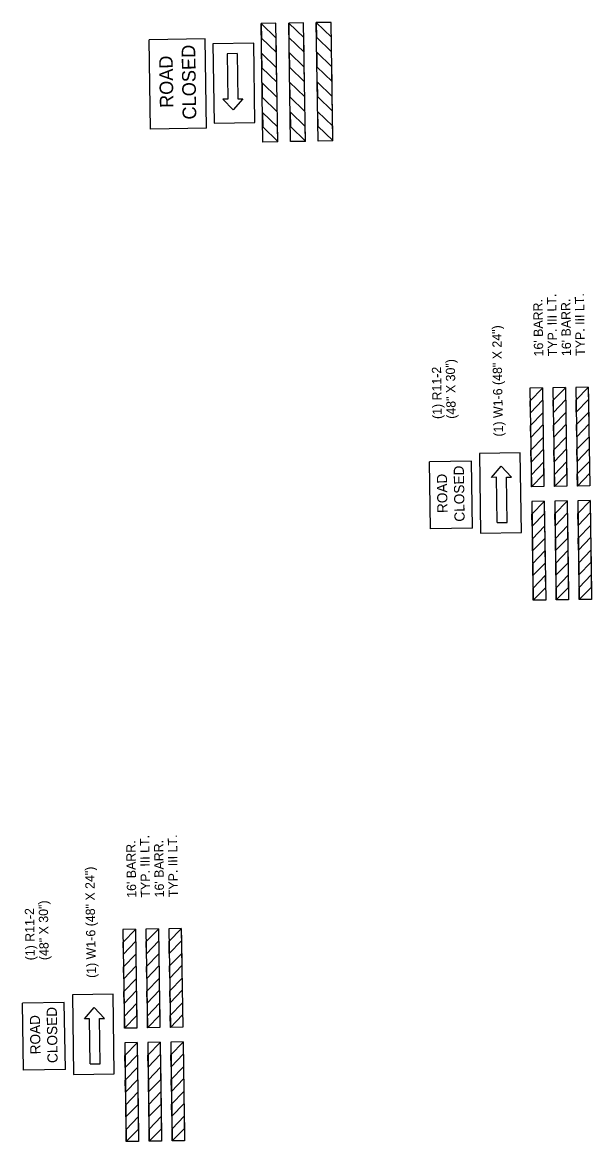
# Model space of a CAD drawing. Extents: x 1770139 to 1773492, y 718230 to 727190.
# Drawn here: x 1773099 to 1773468, y 718477 to 719202 of the extents above; entities that cross this region are included whole.
import ezdxf

# ---------------------------------------------------------------- set-up
doc = ezdxf.new("R2010")
doc.units = 0
doc.layers.add('R_MOT', color=7, linetype='Continuous')

msp = doc.modelspace()

# ---------------------------------------------------------------- linework, layer by layer
at = {"layer": 'R_MOT'}
for p, q in [((1773263.38, 719201.45), (1773253.73, 719201.3)), ((1773254.92, 719124.43), (1773253.73, 719201.3)), ((1773263.36, 719201.39), (1773263.3, 719201.45)), ((1773264.57, 719124.58), (1773263.38, 719201.45)), ((1773281.25, 719201.72), (1773271.62, 719201.58)), ((1773281.25, 719201.72), (1773271.62, 719201.58)), ((1773272.81, 719124.71), (1773271.62, 719201.58)), ((1773282.43, 719124.86), (1773281.25, 719201.72)), ((1773299.08, 719202), (1773289.46, 719201.85)), ((1773290.64, 719124.98), (1773289.46, 719201.85)), ((1773300.26, 719125.13), (1773299.08, 719202)), ((1773217.53, 719191.29), (1773181.32, 719190.73)), ((1773182.22, 719132.77), (1773181.32, 719190.73)), ((1773218.42, 719133.33), (1773217.53, 719191.29)), ((1773238.26, 719181.82), (1773231.72, 719181.72)), ((1773231.72, 719181.72), (1773232.17, 719152.33)), ((1773238.26, 719181.82), (1773238.72, 719152.43)), ((1773232.17, 719152.33), (1773228.9, 719152.28)), ((1773235.55, 719145.21), (1773228.9, 719152.28)), ((1773241.99, 719152.48), (1773235.55, 719145.21)), ((1773238.72, 719152.43), (1773241.99, 719152.48)), ((1773218.42, 719133.33), (1773182.22, 719132.77)), ((1773300.26, 719125.13), (1773290.64, 719124.98)), ((1773264.57, 719124.58), (1773254.92, 719124.43)), ((1773282.43, 719124.86), (1773272.81, 719124.71)), ((1773465.62, 718965.53), (1773457.61, 718965.41)), ((1773457.61, 718965.41), (1773458.59, 718901.39)), ((1773465.62, 718965.53), (1773466.61, 718901.51)), ((1773435.89, 718965.08), (1773427.85, 718964.95)), ((1773427.85, 718964.95), (1773428.84, 718900.93)), ((1773435.89, 718965.08), (1773436.87, 718901.05)), ((1773450.77, 718965.3), (1773442.75, 718965.18)), ((1773442.75, 718965.18), (1773443.74, 718901.16)), ((1773450.77, 718965.3), (1773451.75, 718901.28)), ((1773389.88, 718917.52), (1773362.74, 718917.11)), ((1773363.41, 718873.66), (1773362.74, 718917.11)), ((1773390.55, 718874.08), (1773389.88, 718917.52)), ((1773402.84, 718907.06), (1773409.27, 718914.33)), ((1773409.27, 718914.33), (1773415.93, 718907.26)), ((1773406.11, 718907.11), (1773402.84, 718907.06)), ((1773406.56, 718877.72), (1773406.11, 718907.11)), ((1773412.65, 718907.21), (1773415.93, 718907.26)), ((1773413.11, 718877.82), (1773412.65, 718907.21)), ((1773436.87, 718901.05), (1773428.84, 718900.93)), ((1773436.85, 718901.1), (1773436.8, 718901.05)), ((1773451.75, 718901.28), (1773443.74, 718901.16)), ((1773451.75, 718901.28), (1773443.74, 718901.16)), ((1773466.61, 718901.51), (1773458.59, 718901.39)), ((1773437.02, 718891.55), (1773428.98, 718891.43)), ((1773428.98, 718891.43), (1773429.97, 718827.41)), ((1773437.02, 718891.55), (1773438.01, 718827.53)), ((1773451.9, 718891.78), (1773443.88, 718891.66)), ((1773443.88, 718891.66), (1773444.87, 718827.63)), ((1773451.9, 718891.78), (1773452.89, 718827.76)), ((1773466.75, 718892.01), (1773458.74, 718891.89)), ((1773458.74, 718891.89), (1773459.72, 718827.86)), ((1773466.75, 718892.01), (1773467.74, 718827.99)), ((1773390.55, 718874.08), (1773363.41, 718873.66)), ((1773406.56, 718877.72), (1773413.11, 718877.82)), ((1773437.98, 718827.58), (1773437.94, 718827.53)), ((1773452.89, 718827.76), (1773444.87, 718827.63)), ((1773452.89, 718827.76), (1773444.87, 718827.63)), ((1773467.74, 718827.99), (1773459.72, 718827.86)), ((1773438.01, 718827.53), (1773429.97, 718827.41)), ((1773172.33, 718614.17), (1773164.29, 718614.05)), ((1773164.29, 718614.05), (1773165.27, 718550.03)), ((1773172.33, 718614.17), (1773173.31, 718550.15)), ((1773187.21, 718614.4), (1773179.19, 718614.28)), ((1773179.19, 718614.28), (1773180.18, 718550.26)), ((1773187.21, 718614.4), (1773188.19, 718550.38)), ((1773202.06, 718614.63), (1773194.04, 718614.51)), ((1773194.04, 718614.51), (1773195.03, 718550.48)), ((1773202.06, 718614.63), (1773203.05, 718550.61)), ((1773126.32, 718566.62), (1773099.18, 718566.21)), ((1773126.99, 718523.18), (1773126.32, 718566.62)), ((1773099.85, 718522.76), (1773099.18, 718566.21)), ((1773139.28, 718556.15), (1773145.71, 718563.43)), ((1773145.71, 718563.43), (1773152.37, 718556.36)), ((1773142.55, 718556.2), (1773139.28, 718556.15)), ((1773143, 718526.82), (1773142.55, 718556.2)), ((1773149.09, 718556.31), (1773152.37, 718556.36)), ((1773149.55, 718526.92), (1773149.09, 718556.31)), ((1773173.31, 718550.15), (1773165.27, 718550.03)), ((1773173.29, 718550.2), (1773173.24, 718550.15)), ((1773188.19, 718550.38), (1773180.18, 718550.26)), ((1773188.19, 718550.38), (1773180.18, 718550.26)), ((1773203.05, 718550.61), (1773195.03, 718550.48)), ((1773173.46, 718540.65), (1773165.42, 718540.53)), ((1773165.42, 718540.53), (1773166.41, 718476.5)), ((1773173.46, 718540.65), (1773174.45, 718476.63)), ((1773188.34, 718540.88), (1773180.32, 718540.76)), ((1773180.32, 718540.76), (1773181.31, 718476.73)), ((1773188.34, 718540.88), (1773189.32, 718476.86)), ((1773203.19, 718541.11), (1773195.18, 718540.99)), ((1773195.18, 718540.99), (1773196.16, 718476.96)), ((1773203.19, 718541.11), (1773204.18, 718477.09)), ((1773126.99, 718523.18), (1773099.85, 718522.76)), ((1773143, 718526.82), (1773149.55, 718526.92)), ((1773174.45, 718476.63), (1773166.41, 718476.5)), ((1773174.42, 718476.68), (1773174.37, 718476.63)), ((1773189.32, 718476.86), (1773181.31, 718476.73)), ((1773189.32, 718476.86), (1773181.31, 718476.73)), ((1773204.18, 718477.09), (1773196.16, 718476.96))]:
    msp.add_line(p, q, dxfattribs=at)
for points in [[(1773253.73, 719201.3), (1773253.91, 719191.85), (1773263.65, 719182.4), (1773263.5, 719191.83)], [(1773271.62, 719201.58), (1773271.8, 719192.13), (1773281.54, 719182.68), (1773281.39, 719192.1)], [(1773289.46, 719201.85), (1773289.63, 719192.4), (1773299.37, 719182.95), (1773299.23, 719192.38)], [(1773249.72, 719137.03), (1773248.93, 719188.55), (1773222.58, 719188.15), (1773223.37, 719136.62)], [(1773254.03, 719182.09), (1773254.2, 719172.64), (1773263.94, 719163.2), (1773263.8, 719172.62)], [(1773271.92, 719182.37), (1773272.09, 719172.92), (1773281.84, 719163.47), (1773281.69, 719172.89)], [(1773289.75, 719182.64), (1773289.93, 719173.19), (1773299.67, 719163.75), (1773299.52, 719173.17)], [(1773254.32, 719162.89), (1773254.5, 719153.44), (1773264.24, 719143.99), (1773264.09, 719153.41)], [(1773272.22, 719163.16), (1773272.39, 719153.71), (1773282.13, 719144.27), (1773281.99, 719153.69)], [(1773290.05, 719163.44), (1773290.22, 719153.99), (1773299.97, 719144.54), (1773299.82, 719153.96)], [(1773254.62, 719143.68), (1773254.79, 719134.23), (1773264.54, 719124.78), (1773264.39, 719134.2)], [(1773272.51, 719143.95), (1773272.69, 719134.5), (1773282.43, 719125.06), (1773282.28, 719134.48)], [(1773290.35, 719144.23), (1773290.52, 719134.78), (1773300.26, 719125.33), (1773300.12, 719134.75)], [(1773428.1, 718948.92), (1773428, 718956.79), (1773435.87, 718964.91), (1773435.99, 718957.06)], [(1773443, 718949.15), (1773442.9, 718957.02), (1773450.77, 718965.14), (1773450.89, 718957.29)], [(1773457.85, 718949.38), (1773457.76, 718957.25), (1773465.62, 718965.37), (1773465.74, 718957.52)], [(1773428.34, 718932.92), (1773428.24, 718940.79), (1773436.11, 718948.91), (1773436.23, 718941.06)], [(1773443.24, 718933.15), (1773443.15, 718941.02), (1773451.02, 718949.14), (1773451.14, 718941.29)], [(1773458.1, 718933.38), (1773458, 718941.25), (1773465.87, 718949.37), (1773465.99, 718941.52)], [(1773428.59, 718916.93), (1773428.49, 718924.8), (1773436.36, 718932.91), (1773436.48, 718925.06)], [(1773443.49, 718917.15), (1773443.39, 718925.03), (1773451.26, 718933.14), (1773451.38, 718925.29)], [(1773458.35, 718917.38), (1773458.25, 718925.26), (1773466.12, 718933.37), (1773466.24, 718925.52)], [(1773395.11, 718922.51), (1773395.9, 718870.99), (1773422.25, 718871.39), (1773421.46, 718922.92)], [(1773428.84, 718900.93), (1773428.74, 718908.8), (1773436.61, 718916.91), (1773436.73, 718909.07)], [(1773443.74, 718901.16), (1773443.64, 718909.03), (1773451.51, 718917.14), (1773451.63, 718909.3)], [(1773458.59, 718901.39), (1773458.49, 718909.26), (1773466.36, 718917.37), (1773466.48, 718909.52)], [(1773429.23, 718875.4), (1773429.13, 718883.27), (1773437, 718891.39), (1773437.12, 718883.54)], [(1773444.13, 718875.63), (1773444.03, 718883.5), (1773451.9, 718891.62), (1773452.02, 718883.77)], [(1773458.99, 718875.86), (1773458.89, 718883.73), (1773466.76, 718891.84), (1773466.88, 718884)], [(1773429.48, 718859.4), (1773429.38, 718867.27), (1773437.25, 718875.39), (1773437.37, 718867.54)], [(1773444.38, 718859.63), (1773444.28, 718867.5), (1773452.15, 718875.62), (1773452.27, 718867.77)], [(1773459.23, 718859.86), (1773459.13, 718867.73), (1773467, 718875.85), (1773467.12, 718868)], [(1773429.72, 718843.4), (1773429.62, 718851.27), (1773437.49, 718859.39), (1773437.61, 718851.54)], [(1773444.62, 718843.63), (1773444.53, 718851.5), (1773452.39, 718859.62), (1773452.52, 718851.77)], [(1773459.48, 718843.86), (1773459.38, 718851.73), (1773467.25, 718859.85), (1773467.37, 718852)], [(1773429.97, 718827.41), (1773429.87, 718835.28), (1773437.74, 718843.39), (1773437.86, 718835.54)], [(1773444.87, 718827.63), (1773444.77, 718835.51), (1773452.64, 718843.62), (1773452.76, 718835.77)], [(1773459.72, 718827.86), (1773459.63, 718835.74), (1773467.5, 718843.85), (1773467.62, 718836)], [(1773164.53, 718598.02), (1773164.44, 718605.89), (1773172.31, 718614.01), (1773172.43, 718606.16)], [(1773179.44, 718598.25), (1773179.34, 718606.12), (1773187.21, 718614.24), (1773187.33, 718606.39)], [(1773194.29, 718598.48), (1773194.19, 718606.35), (1773202.06, 718614.46), (1773202.18, 718606.62)], [(1773164.78, 718582.02), (1773164.68, 718589.89), (1773172.55, 718598.01), (1773172.67, 718590.16)], [(1773179.68, 718582.25), (1773179.59, 718590.12), (1773187.45, 718598.24), (1773187.58, 718590.39)], [(1773194.54, 718582.48), (1773194.44, 718590.35), (1773202.31, 718598.47), (1773202.43, 718590.62)], [(1773165.03, 718566.02), (1773164.93, 718573.9), (1773172.8, 718582.01), (1773172.92, 718574.16)], [(1773179.93, 718566.25), (1773179.83, 718574.13), (1773187.7, 718582.24), (1773187.82, 718574.39)], [(1773194.78, 718566.48), (1773194.69, 718574.35), (1773202.56, 718582.47), (1773202.68, 718574.62)], [(1773131.54, 718571.61), (1773132.34, 718520.09), (1773158.69, 718520.49), (1773157.89, 718572.02)], [(1773195.03, 718550.48), (1773194.93, 718558.36), (1773202.8, 718566.47), (1773202.92, 718558.62)], [(1773165.27, 718550.03), (1773165.18, 718557.9), (1773173.04, 718566.01), (1773173.17, 718558.16)], [(1773180.18, 718550.26), (1773180.08, 718558.13), (1773187.95, 718566.24), (1773188.07, 718558.39)], [(1773165.67, 718524.5), (1773165.57, 718532.37), (1773173.44, 718540.48), (1773173.56, 718532.64)], [(1773180.57, 718524.73), (1773180.47, 718532.6), (1773188.34, 718540.71), (1773188.46, 718532.87)], [(1773195.42, 718524.96), (1773195.33, 718532.83), (1773203.19, 718540.94), (1773203.32, 718533.1)], [(1773165.91, 718508.5), (1773165.82, 718516.37), (1773173.68, 718524.49), (1773173.81, 718516.64)], [(1773180.82, 718508.73), (1773180.72, 718516.6), (1773188.59, 718524.72), (1773188.71, 718516.87)], [(1773195.67, 718508.96), (1773195.57, 718516.83), (1773203.44, 718524.94), (1773203.56, 718517.1)], [(1773166.16, 718492.5), (1773166.06, 718500.37), (1773173.93, 718508.49), (1773174.05, 718500.64)], [(1773181.06, 718492.73), (1773180.97, 718500.6), (1773188.83, 718508.72), (1773188.95, 718500.87)], [(1773195.92, 718492.96), (1773195.82, 718500.83), (1773203.69, 718508.95), (1773203.81, 718501.1)], [(1773166.41, 718476.5), (1773166.31, 718484.38), (1773174.18, 718492.49), (1773174.3, 718484.64)], [(1773181.31, 718476.73), (1773181.21, 718484.61), (1773189.08, 718492.72), (1773189.2, 718484.87)], [(1773196.16, 718476.96), (1773196.07, 718484.83), (1773203.93, 718492.95), (1773204.06, 718485.1)]]:
    msp.add_lwpolyline(points, close=True, dxfattribs=at)

# ---------------------------------------------------------------- texts
for s, height, p in [('CLOSED', 8.817, (1773211.79, 719139.08)), ('ROAD', 8.774, (1773196.98, 719146.63)), ('TYP. III LT.', 6, (1773445.46, 718985.63)), ('TYP. III LT.', 6, (1773463.46, 718985.91)), ("16' BARR.", 6, (1773436.46, 718985.49)), ("16' BARR.", 6, (1773454.46, 718985.77)), ('(1) W1-6 (48" X 24")', 6, (1773410.39, 718933.57)), ('(48" X 30")', 6, (1773379.81, 718945.09)), ('(1) R11-2', 6, (1773370.81, 718944.95)), ('ROAD', 6.577, (1773374.48, 718884.05)), ('CLOSED', 6.61, (1773385.58, 718878.39)), ("16' BARR.", 6, (1773172.9, 718634.59)), ('TYP. III LT.', 6, (1773181.9, 718634.73)), ("16' BARR.", 6, (1773190.9, 718634.87)), ('TYP. III LT.', 6, (1773199.9, 718635.01)), ('(1) W1-6 (48" X 24")', 6, (1773146.83, 718582.67)), ('(48" X 30")', 6, (1773116.25, 718594.19)), ('(1) R11-2', 6, (1773107.25, 718594.05)), ('CLOSED', 6.61, (1773122.02, 718527.49)), ('ROAD', 6.577, (1773110.92, 718533.15))]:
    msp.add_text(s, height=height, rotation=90.88269, dxfattribs=at).set_placement(p)

doc.saveas('drawing.dxf')
